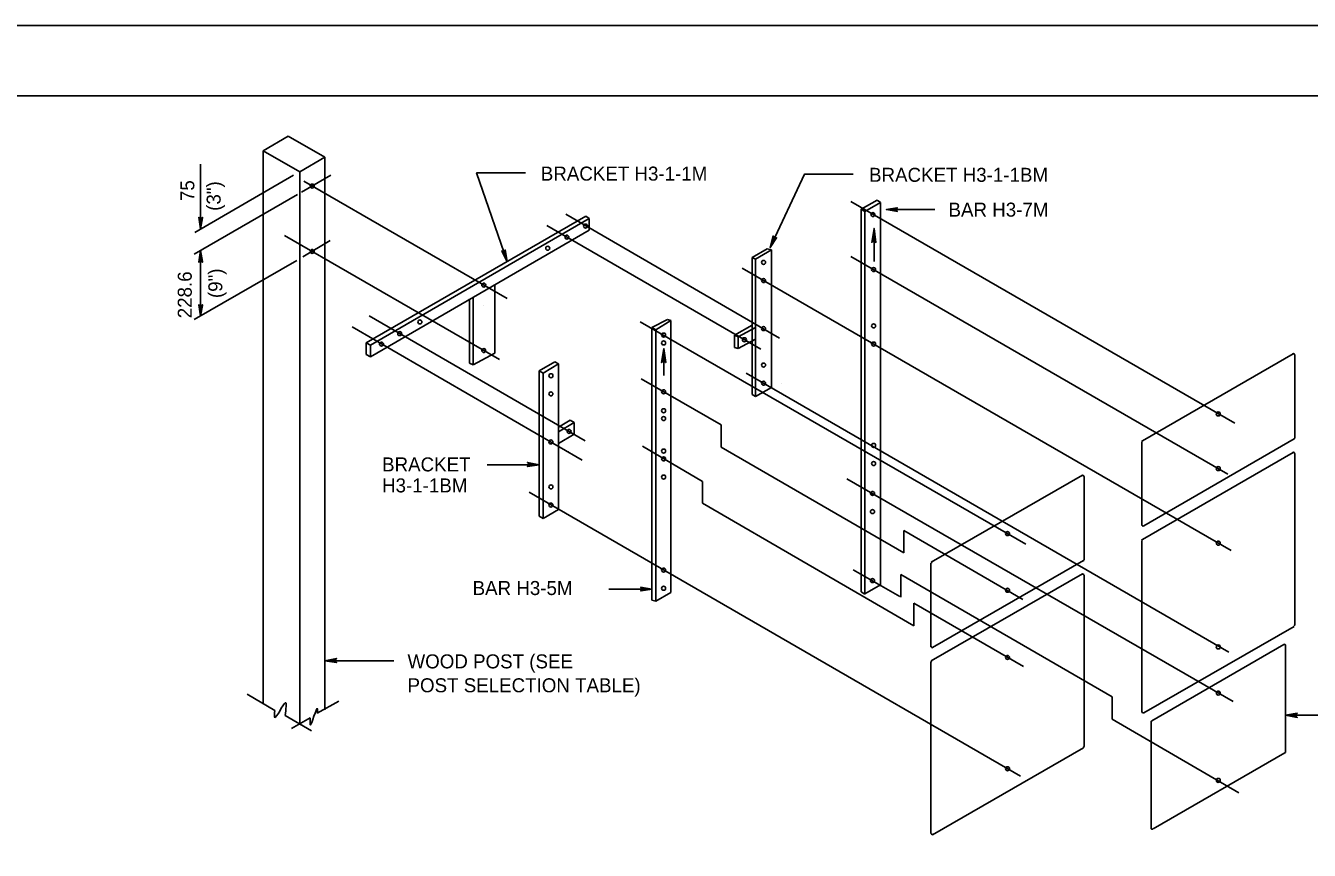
# Model space of a CAD drawing. Extents: x 649454 to 651200, y 295188 to 295782.
# Drawn here: x 650563.3 to 650838.3, y 295605 to 295781.6 of the extents above; entities that cross this region are included whole.
import ezdxf

# ---------------------------------------------------------------- set-up
doc = ezdxf.new("R2010")
doc.units = 0
for name, color, linetype in [('1', 7, 'Continuous'), ('2', 7, 'Continuous'), ('3', 7, 'Continuous'), ('PLT-BNDY', 7, 'Continuous')]:
    doc.layers.add(name, color=color, linetype=linetype)

msp = doc.modelspace()

# ---------------------------------------------------------------- linework, layer by layer
at = {"layer": '1'}
msp.add_line((650335.31, 295766.63), (651121.31, 295766.63), dxfattribs=at)
at = {"layer": '2'}
for points in [[(650670.39, 295750.1), (650659.94, 295750.1), (650666.44, 295731.1)], [(650740.59, 295749.85), (650730.19, 295749.85), (650722.81, 295734.1)], [(650749.94, 295741.97), (650749.94, 295742.1), (650747.69, 295742.22), (650749.94, 295741.97), (650750.06, 295741.85), (650747.69, 295742.22), (650749.94, 295742.35), (650749.94, 295742.6), (650747.69, 295742.22), (650750.06, 295742.6), (650749.94, 295742.6)], [(650758.06, 295742.22), (650747.69, 295742.22)], [(650724.06, 295736.1), (650723.81, 295736.1), (650722.81, 295734.1), (650724.06, 295736.1), (650724.19, 295736.22), (650722.81, 295734.1), (650723.69, 295736.22), (650723.56, 295736.35), (650722.81, 295734.1), (650723.44, 295736.6), (650723.56, 295736.35)], [(650665.94, 295733.47), (650665.81, 295733.35), (650666.44, 295731.1), (650665.94, 295733.47), (650666.06, 295733.6), (650666.44, 295731.1), (650665.56, 295733.22), (650665.44, 295733.35), (650666.44, 295731.1), (650665.31, 295733.35), (650665.44, 295733.35)], [(650673.31, 295687.6), (650662.19, 295687.6)], [(650670.94, 295687.97), (650671.06, 295687.72), (650673.31, 295687.6), (650670.94, 295687.97), (650670.81, 295688.1), (650673.31, 295687.6), (650671.06, 295687.47), (650671.06, 295687.35), (650673.31, 295687.6), (650670.81, 295687.22), (650671.06, 295687.35)], [(650697.44, 295660.97), (650688.24, 295660.97)], [(650695.19, 295661.22), (650695.19, 295661.1), (650697.44, 295660.97), (650695.19, 295661.22), (650695.06, 295661.35), (650697.44, 295660.97), (650695.19, 295660.85), (650695.19, 295660.6), (650697.44, 295660.97), (650695.06, 295660.6), (650695.19, 295660.6)], [(650629.81, 295645.35), (650629.69, 295645.47), (650627.44, 295645.6), (650629.81, 295645.35), (650629.94, 295645.22), (650627.44, 295645.6), (650629.69, 295645.72), (650629.81, 295645.97), (650627.44, 295645.6), (650629.94, 295646.1), (650629.81, 295645.97)], [(650642.21, 295645.6), (650627.44, 295645.6)], [(650835.56, 295633.6), (650835.44, 295633.85), (650833.19, 295633.97), (650835.56, 295633.6), (650835.69, 295633.47), (650833.19, 295633.97), (650835.44, 295634.1), (650835.56, 295634.22), (650833.19, 295633.97), (650835.69, 295634.35), (650835.56, 295634.22)], [(650843.26, 295633.97), (650833.19, 295633.97)]]:
    msp.add_lwpolyline(points, dxfattribs=at)
at = {"layer": '3'}
for p, q in [((650614.19, 295754.85), (650619.56, 295757.97)), ((650627.44, 295753.47), (650619.56, 295757.97)), ((650614.19, 295636.6), (650614.19, 295754.85)), ((650622.06, 295750.35), (650614.19, 295754.85)), ((650622.06, 295750.35), (650627.44, 295753.47)), ((650627.44, 295635.1), (650627.44, 295753.47)), ((650600.81, 295738.1), (650600.81, 295751.98)), ((650622.06, 295631.97), (650622.06, 295750.35)), ((650599.56, 295737.35), (650620.69, 295749.6)), ((650622.44, 295745.97), (650628.69, 295749.6)), ((650666.44, 295723.22), (650622.94, 295748.35)), ((650599.44, 295732.72), (650621.56, 295745.47)), ((650624.81, 295747.22), (650624.81, 295747.22)), ((650822.31, 295696.47), (650740.06, 295743.97)), ((650742.31, 295742.35), (650745.69, 295744.22)), ((650742.31, 295660.35), (650742.31, 295742.35)), ((650743.06, 295741.85), (650742.31, 295742.35)), ((650743.06, 295741.85), (650746.44, 295743.72)), ((650746.44, 295743.72), (650745.69, 295744.22)), ((650746.44, 295661.85), (650746.44, 295743.72)), ((650636.31, 295713.72), (650683.31, 295740.85)), ((650637.19, 295713.22), (650684.06, 295740.35)), ((650724.81, 295714.72), (650679.06, 295741.22)), ((650682.69, 295740.6), (650682.69, 295740.6)), ((650684.06, 295740.35), (650683.31, 295740.85)), ((650684.06, 295737.85), (650684.06, 295740.35)), ((650743.06, 295659.85), (650743.06, 295741.85)), ((650664.81, 295710.1), (650618.81, 295736.72)), ((650637.19, 295710.72), (650684.06, 295737.85)), ((650720.81, 295712.35), (650674.94, 295738.85)), ((650683.69, 295737.6), (650683.69, 295737.6)), ((650745.06, 295731.1), (650745.06, 295738.22)), ((650622.69, 295732.1), (650628.56, 295735.6)), ((650718.94, 295731.97), (650722.19, 295733.85)), ((650723.06, 295733.6), (650722.19, 295733.85)), ((650599.44, 295718.72), (650621.44, 295731.35)), ((650600.81, 295719.47), (650600.81, 295733.47)), ((650624.81, 295733.35), (650624.81, 295733.35)), ((650718.94, 295702.6), (650718.94, 295731.97)), ((650719.69, 295731.6), (650718.94, 295731.97)), ((650719.69, 295731.6), (650723.06, 295733.6)), ((650719.69, 295702.22), (650719.69, 295731.6)), ((650723.06, 295704.1), (650723.06, 295733.6)), ((650820.81, 295685.6), (650740.06, 295732.22)), ((650821.56, 295669.22), (650716.81, 295729.72)), ((650663.81, 295711.47), (650663.81, 295726.1)), ((650654.94, 295723.6), (650654.94, 295723.6)), ((650656.31, 295724.35), (650656.31, 295724.35)), ((650658.44, 295709.35), (650658.44, 295723.1)), ((650659.19, 295708.97), (650659.19, 295723.47)), ((650649.31, 295720.35), (650649.31, 295720.35)), ((650650.81, 295721.22), (650650.81, 295721.22)), ((650652.19, 295721.85), (650652.19, 295721.85)), ((650653.56, 295722.72), (650653.56, 295722.72)), ((650661.44, 295721.72), (650661.44, 295721.72)), ((650683.19, 295692.72), (650636.94, 295719.47)), ((650645.31, 295718.1), (650645.31, 295718.1)), ((650646.69, 295718.72), (650646.69, 295718.72)), ((650648.06, 295719.6), (650648.06, 295719.6)), ((650777.56, 295670.6), (650694.94, 295718.22)), ((650697.44, 295716.97), (650700.81, 295718.72)), ((650698.31, 295716.47), (650701.56, 295718.47)), ((650701.56, 295718.47), (650700.81, 295718.72)), ((650701.56, 295660.22), (650701.56, 295718.47)), ((650715.19, 295715.35), (650718.94, 295717.47)), ((650682.56, 295688.6), (650633.31, 295717.1)), ((650639.94, 295714.85), (650639.94, 295714.85)), ((650641.19, 295715.6), (650641.19, 295715.6)), ((650642.56, 295716.35), (650642.56, 295716.35)), ((650643.44, 295715.6), (650643.44, 295715.6)), ((650643.94, 295717.22), (650643.94, 295717.22)), ((650697.44, 295658.6), (650697.44, 295716.97)), ((650698.31, 295716.47), (650697.44, 295716.97)), ((650698.31, 295658.35), (650698.31, 295716.47)), ((650715.94, 295714.97), (650715.19, 295715.35)), ((650715.19, 295712.72), (650715.19, 295715.35)), ((650715.94, 295714.97), (650719.69, 295716.97)), ((650715.94, 295712.47), (650715.94, 295714.97)), ((650637.19, 295713.22), (650636.31, 295713.72)), ((650636.31, 295711.22), (650636.31, 295713.72)), ((650637.19, 295710.72), (650637.19, 295713.22)), ((650637.19, 295713.22), (650637.19, 295713.22)), ((650638.44, 295714.1), (650638.44, 295714.1)), ((650661.44, 295712.1), (650661.44, 295712.1)), ((650700.06, 295712.47), (650700.06, 295706.72)), ((650715.94, 295712.47), (650715.19, 295712.72)), ((650715.94, 295712.47), (650719.69, 295714.47)), ((650637.19, 295710.72), (650636.31, 295711.22)), ((650659.19, 295708.97), (650658.44, 295709.35)), ((650659.19, 295708.97), (650663.81, 295711.47)), ((650673.31, 295707.72), (650676.69, 295709.6)), ((650674.19, 295707.22), (650677.44, 295709.22)), ((650677.44, 295709.22), (650676.69, 295709.6)), ((650677.44, 295677.97), (650677.44, 295709.22)), ((650802.56, 295692.72), (650834.81, 295711.35)), ((650835.19, 295693.35), (650835.19, 295711.1)), ((650673.31, 295676.6), (650673.31, 295707.72)), ((650674.19, 295707.22), (650673.31, 295707.72)), ((650674.19, 295676.1), (650674.19, 295707.22)), ((650821.06, 295647.47), (650717.69, 295707.22)), ((650712.31, 295696.1), (650695.19, 295705.97)), ((650719.69, 295702.22), (650723.06, 295704.1)), ((650725.31, 295704.97), (650725.31, 295704.97)), ((650719.69, 295702.22), (650718.94, 295702.6)), ((650677.44, 295695.6), (650679.94, 295697.1)), ((650677.44, 295694.6), (650680.81, 295696.6)), ((650680.81, 295696.6), (650679.94, 295697.1)), ((650680.81, 295694.1), (650680.81, 295696.6)), ((650712.31, 295691.35), (650712.31, 295696.1)), ((650677.44, 295692.1), (650680.81, 295694.1)), ((650679.69, 295694.72), (650679.69, 295694.72)), ((650802.81, 295674.47), (650835.06, 295693.1)), ((650679.69, 295690.47), (650679.69, 295690.47)), ((650708.31, 295683.97), (650695.44, 295691.6)), ((650751.44, 295668.72), (650712.31, 295691.35)), ((650802.44, 295674.72), (650802.44, 295692.47)), ((650802.56, 295671.6), (650834.81, 295690.22)), ((650835.19, 295653.22), (650835.19, 295689.97)), ((650821.94, 295636.85), (650739.19, 295684.6)), ((650757.31, 295666.72), (650789.69, 295685.35)), ((650790.06, 295667.22), (650790.06, 295685.1)), ((650776.44, 295620.85), (650671.19, 295681.72)), ((650708.31, 295679.35), (650708.31, 295683.97)), ((650753.56, 295653.1), (650708.31, 295679.35)), ((650674.19, 295676.1), (650673.31, 295676.6)), ((650674.19, 295676.1), (650677.44, 295677.97)), ((650776.94, 295658.72), (650751.44, 295673.47)), ((650751.44, 295668.72), (650751.44, 295673.47)), ((650802.44, 295634.6), (650802.44, 295671.35)), ((650740.56, 295665.1), (650750.56, 295659.35)), ((650757.19, 295648.6), (650757.19, 295666.47)), ((650757.56, 295648.47), (650789.94, 295667.1)), ((650750.81, 295659.22), (650750.81, 295664.1)), ((650796.06, 295637.85), (650750.81, 295664.1)), ((650757.31, 295645.6), (650789.69, 295664.22)), ((650790.06, 295627.22), (650790.06, 295663.97)), ((650698.31, 295658.35), (650701.56, 295660.22)), ((650743.06, 295659.85), (650742.31, 295660.35)), ((650743.06, 295659.97), (650746.44, 295661.85)), ((650698.31, 295658.35), (650697.44, 295658.6)), ((650777.06, 295644.35), (650753.56, 295657.97)), ((650753.56, 295653.1), (650753.56, 295657.97)), ((650802.81, 295634.47), (650835.06, 295652.97)), ((650804.56, 295632.72), (650832.81, 295649.1)), ((650833.19, 295626.1), (650833.19, 295648.97)), ((650757.19, 295608.6), (650757.19, 295645.35)), ((650616.69, 295634.97), (650610.81, 295638.47)), ((650796.06, 295633.1), (650796.06, 295637.85)), ((650625.81, 295634.35), (650630.44, 295636.97)), ((650624.56, 295630.6), (650618.94, 295633.85)), ((650620.31, 295631.1), (650624.31, 295633.35)), ((650823.19, 295617.35), (650796.06, 295633.1)), ((650804.44, 295609.85), (650804.44, 295632.47)), ((650757.56, 295608.35), (650789.94, 295626.97)), ((650804.81, 295609.6), (650833.06, 295625.85))]:
    msp.add_line(p, q, dxfattribs=at)
for points in [[(650601.19, 295740.47), (650600.94, 295740.35), (650600.81, 295738.1), (650601.19, 295740.47), (650601.19, 295740.6), (650600.81, 295738.1), (650600.69, 295740.35), (650600.56, 295740.47), (650600.81, 295738.1), (650600.44, 295740.6), (650600.56, 295740.47)], [(650744.69, 295735.35), (650744.81, 295735.47), (650745.06, 295738.22), (650744.69, 295735.35), (650744.56, 295735.22), (650745.06, 295738.22), (650745.19, 295735.47), (650745.19, 295735.35), (650745.06, 295738.22), (650745.44, 295735.22), (650745.19, 295735.35)], [(650600.56, 295731.1), (650600.69, 295731.1), (650600.81, 295733.47), (650600.56, 295731.1), (650600.44, 295730.97), (650600.81, 295733.47), (650600.94, 295731.1), (650601.19, 295731.1), (650600.81, 295733.47), (650601.19, 295730.97), (650601.19, 295731.1)], [(650601.19, 295721.72), (650600.94, 295721.72), (650600.81, 295719.47), (650601.19, 295721.72), (650601.19, 295721.85), (650600.81, 295719.47), (650600.69, 295721.72), (650600.56, 295721.72), (650600.81, 295719.47), (650600.44, 295721.85), (650600.56, 295721.72)], [(650699.69, 295709.6), (650699.94, 295709.6), (650700.06, 295712.47), (650699.69, 295709.6), (650699.56, 295709.47), (650700.06, 295712.47), (650700.19, 295709.6), (650700.31, 295709.6), (650700.06, 295712.47), (650700.44, 295709.47), (650700.31, 295709.6)]]:
    msp.add_lwpolyline(points, dxfattribs=at)
for centre in [(650624.72, 295747.28), (650744.81, 295741.18), (650679.26, 295736.33), (650683.26, 295738.71), (650675.15, 295733.96), (650624.72, 295733.27), (650721.39, 295730.93), (650744.96, 295729.39), (650661.47, 295726.06), (650721.39, 295727.04), (650647.78, 295718.16), (650744.96, 295717.32), (650643.46, 295715.67), (650699.98, 295715.36), (650717.28, 295714.37), (650721.39, 295716.74), (650639.56, 295713.42), (650661.47, 295712.05), (650699.98, 295713.67), (650744.96, 295713.43), (650721.39, 295708.94), (650675.85, 295706.66), (650699.98, 295703.22), (650721.39, 295705.05), (650675.84, 295702.77), (650699.98, 295699.16), (650818.79, 295698.46), (650699.98, 295697.48), (650675.84, 295692.47), (650679.74, 295694.72), (650699.98, 295690.52), (650744.96, 295691.74), (650699.98, 295688.84), (650744.96, 295687.85), (650818.79, 295686.75), (650699.98, 295684.95), (650675.85, 295682.84), (650744.72, 295681.44), (650675.84, 295678.95), (650744.72, 295677.55), (650773.64, 295672.83), (650818.79, 295670.79), (650699.98, 295665.02), (650744.72, 295662.76), (650699.98, 295661.12), (650773.64, 295660.69), (650818.79, 295648.55), (650773.64, 295646.31), (650818.79, 295638.67), (650773.64, 295622.49), (650818.79, 295619.98)]:
    msp.add_circle(centre, 0.428, dxfattribs=at)
for centre, start, end in [((650834.89, 295711.13), 0, 119.9917), ((650802.69, 295692.54), 119.9995, 180), ((650834.89, 295693.28), 299.9933, 0), ((650834.89, 295690.01), 0, 119.9855), ((650789.74, 295685.07), 0, 119.9917), ((650802.69, 295674.69), 180, 299.9946), ((650802.69, 295671.42), 120.0061, 180), ((650757.54, 295666.48), 119.9995, 180), ((650789.74, 295667.22), 299.9933, 0), ((650789.74, 295663.95), 0, 119.999), ((650834.89, 295653.28), 299.9962, 0), ((650757.54, 295648.63), 180, 299.9946), ((650832.94, 295648.88), 0, 119.9857), ((650757.54, 295645.36), 120.001, 180), ((650802.69, 295634.69), 180, 299.9902), ((650804.63, 295632.55), 119.9982, 180), ((650789.74, 295627.22), 299.9789, 0), ((650832.94, 295626.1), 299.9948, 0), ((650757.54, 295608.63), 180, 299.9917), ((650804.63, 295609.76), 180, 299.9954)]:
    msp.add_arc(centre, 0.249, start, end, dxfattribs=at)
for points in [[(650616.69, 295634.97), (650616.69, 295633.47), (650618.94, 295636.6), (650618.94, 295633.85)], [(650624.31, 295633.35), (650624.31, 295631.85), (650625.81, 295635.35), (650625.81, 295634.35)]]:
    msp.add_spline(points, degree=3, dxfattribs=at)
at = {"layer": 'PLT-BNDY'}
msp.add_lwpolyline([(650295.31, 295781.63), (651136.31, 295781.63), (651136.31, 295187.63), (650295.31, 295187.63)], close=True, dxfattribs=at)

# ---------------------------------------------------------------- texts
at = {"layer": '3'}
for s, p in [('BRACKET H3-1-1M', (650673.68, 295748.44)), ('BRACKET H3-1-1BM', (650743.98, 295748.18)), ('BAR H3-7M', (650761, 295740.72)), ('BRACKET', (650639.68, 295686.16)), ('H3-1-1BM', (650639.68, 295681.66)), ('BAR H3-5M', (650659.07, 295659.68)), ('WOOD POST (SEE', (650645.13, 295643.97)), ('POST SELECTION TABLE)', (650645.13, 295638.85))]:
    msp.add_text(s, height=3, dxfattribs=at).set_placement(p)
for s, p in [('75', (650599.47, 295744.06)), ('(3")', (650605.11, 295741.97)), ('228.6', (650598.92, 295718.96)), ('(9")', (650605.47, 295723.29))]:
    msp.add_text(s, height=3, rotation=90, dxfattribs=at).set_placement(p)

doc.saveas('drawing.dxf')
